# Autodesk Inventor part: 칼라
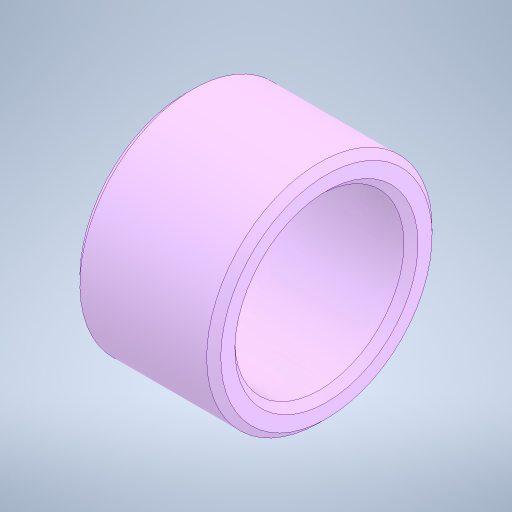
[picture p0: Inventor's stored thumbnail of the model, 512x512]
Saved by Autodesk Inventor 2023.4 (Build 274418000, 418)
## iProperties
Created: 2024-05
Part Number: 칼라
Material: 강철, 합금
Document SubType Name: Modeling
Designer: EDU-001
Density: 7.73 g/cm^3
Appearance: 기본값
Author: jhkim
Sending System: Autodesk Inventor 2025
Preprocessor: ST-DEVELOPER v20
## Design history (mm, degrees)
node "칼라1"
node "솔리드2"
node "솔리드1"
